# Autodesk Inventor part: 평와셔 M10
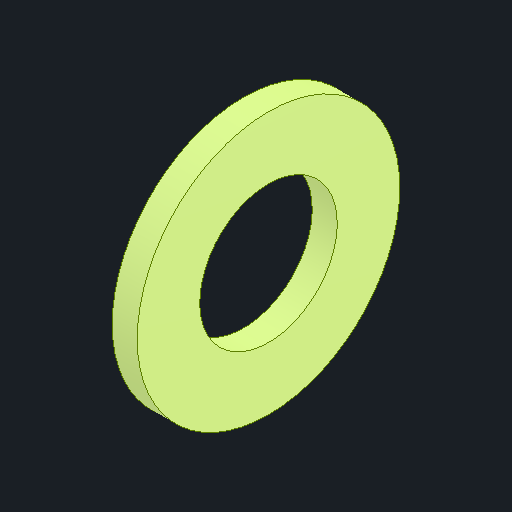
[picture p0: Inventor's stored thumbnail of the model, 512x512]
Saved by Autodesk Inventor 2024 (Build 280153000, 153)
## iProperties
Created: 2025-02
Part Number: 평와셔 M10
Material: 강철, 연강
Description: 평면 와셔
Document SubType Name: Modeling
Designer: kh_501
Density: 7.85 g/cm^3
Appearance: 기본값
Author: jhkim
Sending System: Autodesk Inventor 2025
Preprocessor: ST-DEVELOPER v20
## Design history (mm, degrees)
node "평와셔 M101"
node "솔리드1"
body "Solid1"
